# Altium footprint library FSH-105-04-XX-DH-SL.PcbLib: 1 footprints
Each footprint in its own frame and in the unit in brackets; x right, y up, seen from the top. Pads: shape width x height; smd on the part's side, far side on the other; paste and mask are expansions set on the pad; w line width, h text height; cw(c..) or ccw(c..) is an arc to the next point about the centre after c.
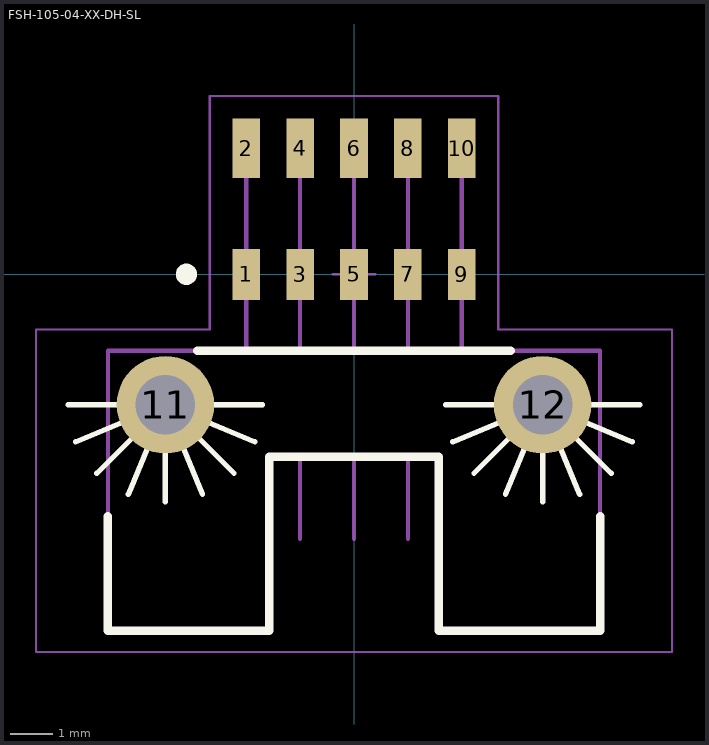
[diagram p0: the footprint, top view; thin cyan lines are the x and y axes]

## FSH-105-04-XX-DH-SL [mm] "1.27mm pitch, 10 pin, header; shrouded, w/solder locks"
height 3.94
pads (12):
  rect 0.65x1.2 smd mask+0: 1(-2.54,0) 3(-1.27,0) 5(0,0) 7(1.27,0) 9(2.54,0)
  rect 0.65x1.4 smd mask+0: 2(-2.54,2.972) 4(-1.27,2.972) 6(0,2.972) 8(1.27,2.972) 10(2.54,2.972)
  round 2.3 hole 1.4 mask+0: 11(-4.445,-3.073) 12(4.445,-3.073)
Top Layer:
  region: -5.461,-3.073 -3.421,-3.074 -3.42,-3.081 -3.455,-3.347 -3.557,-3.594 -3.72,-3.806 -3.933,-3.969 -4.18,-4.071 -4.445,-4.106 -4.71,-4.071 -4.957,-3.969 -5.17,-3.806 -5.333,-3.594 -5.435,-3.347 -5.47,-3.081 -5.469,-3.072
  region: 3.429,-3.073 5.469,-3.074 5.47,-3.081 5.435,-3.347 5.333,-3.594 5.17,-3.806 4.957,-3.969 4.71,-4.071 4.445,-4.106 4.18,-4.071 3.933,-3.969 3.72,-3.806 3.557,-3.594 3.455,-3.347 3.42,-3.081 3.421,-3.072
Top Overlay:
  circle w0.25: c-3.95,0 r0.125
  lines w0.127: -6.731,-3.073 -4.445,-3.073 ; -6.564,-3.948 -4.445,-3.073 ; -6.061,-4.69 -4.445,-3.073 ; -5.32,-5.185 -4.445,-3.073 ; -4.445,-5.359 -4.445,-3.073 ; -3.57,-5.185 -4.445,-3.073 ; -2.829,-4.69 -4.445,-3.073 ; -2.334,-3.948 -4.445,-3.073 ; -2.159,-3.073 -4.445,-3.073 ; 2.159,-3.073 4.445,-3.073 ; 2.326,-3.948 4.445,-3.073 ; 2.829,-4.69 4.445,-3.073 ; 3.57,-5.185 4.445,-3.073 ; 4.445,-5.359 4.445,-3.073 ; 5.32,-5.185 4.445,-3.073 ; 6.061,-4.69 4.445,-3.073 ; 6.556,-3.948 4.445,-3.073 ; 6.731,-3.073 4.445,-3.073
  lines w0.2: -5.8,-5.7 -5.8,-8.4 -2,-8.4 -2,-4.3 2,-4.3 2,-8.4 5.8,-8.4 5.8,-5.7 ; -3.7,-1.8 3.7,-1.8
Top Paste:
  drawing of 12 lines, arcs and shapes, not listed
Mechanical 12:
  lines w0.001: -5.8,-8.4 -2.007,-8.4 -2.007,-4.3 2,-4.3 2,-8.4 5.8,-8.4 5.8,-1.8 -5.8,-1.8 -5.8,-8.4
Mechanical 13:
  lines w0.1: -2.54,-1.8 -2.54,2.972 ; -1.27,-6.236 -1.27,-4.3 ; -1.27,-1.8 -1.27,2.972 ; 0,-6.236 0,-4.3 ; 0,-1.8 0,2.972 ; 1.27,-6.236 1.27,-4.3 ; 1.27,-1.8 1.27,2.972 ; 2.54,-1.8 2.54,2.972 ; -5.8,-8.4 -2.007,-8.4 -2.007,-4.3 2,-4.3 2,-8.4 5.8,-8.4 5.8,-1.8 -5.8,-1.8 -5.8,-8.4
  lines w0.127: -4.445,-3.073 -2.159,-3.073 -4.445,-3.073
  text ".Designator" at 0.254,0.254 h1.52
Mechanical 15:
  lines w0.05: -0.5,0 0.5,0 ; 0,-0.5 0,0.5 ; -7.5,-8.9 -7.5,-1.3 -3.4,-1.3 -3.4,4.2 3.4,4.2 3.4,-1.3 7.5,-1.3 7.5,-8.9 -7.5,-8.9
